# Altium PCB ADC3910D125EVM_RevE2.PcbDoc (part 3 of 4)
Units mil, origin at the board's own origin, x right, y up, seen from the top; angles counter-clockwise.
Board outline 4000 x 2716.54 mil, 6 copper layers (Top Layer, L2 GND, L3 PWR, L4 PWR, L5 GND, Bottom Layer), stack 60.99 mil thick; 318 components, 203 nets, 1298 pads, 559 vias.
Unrouted connection lines stored in the file: 5.
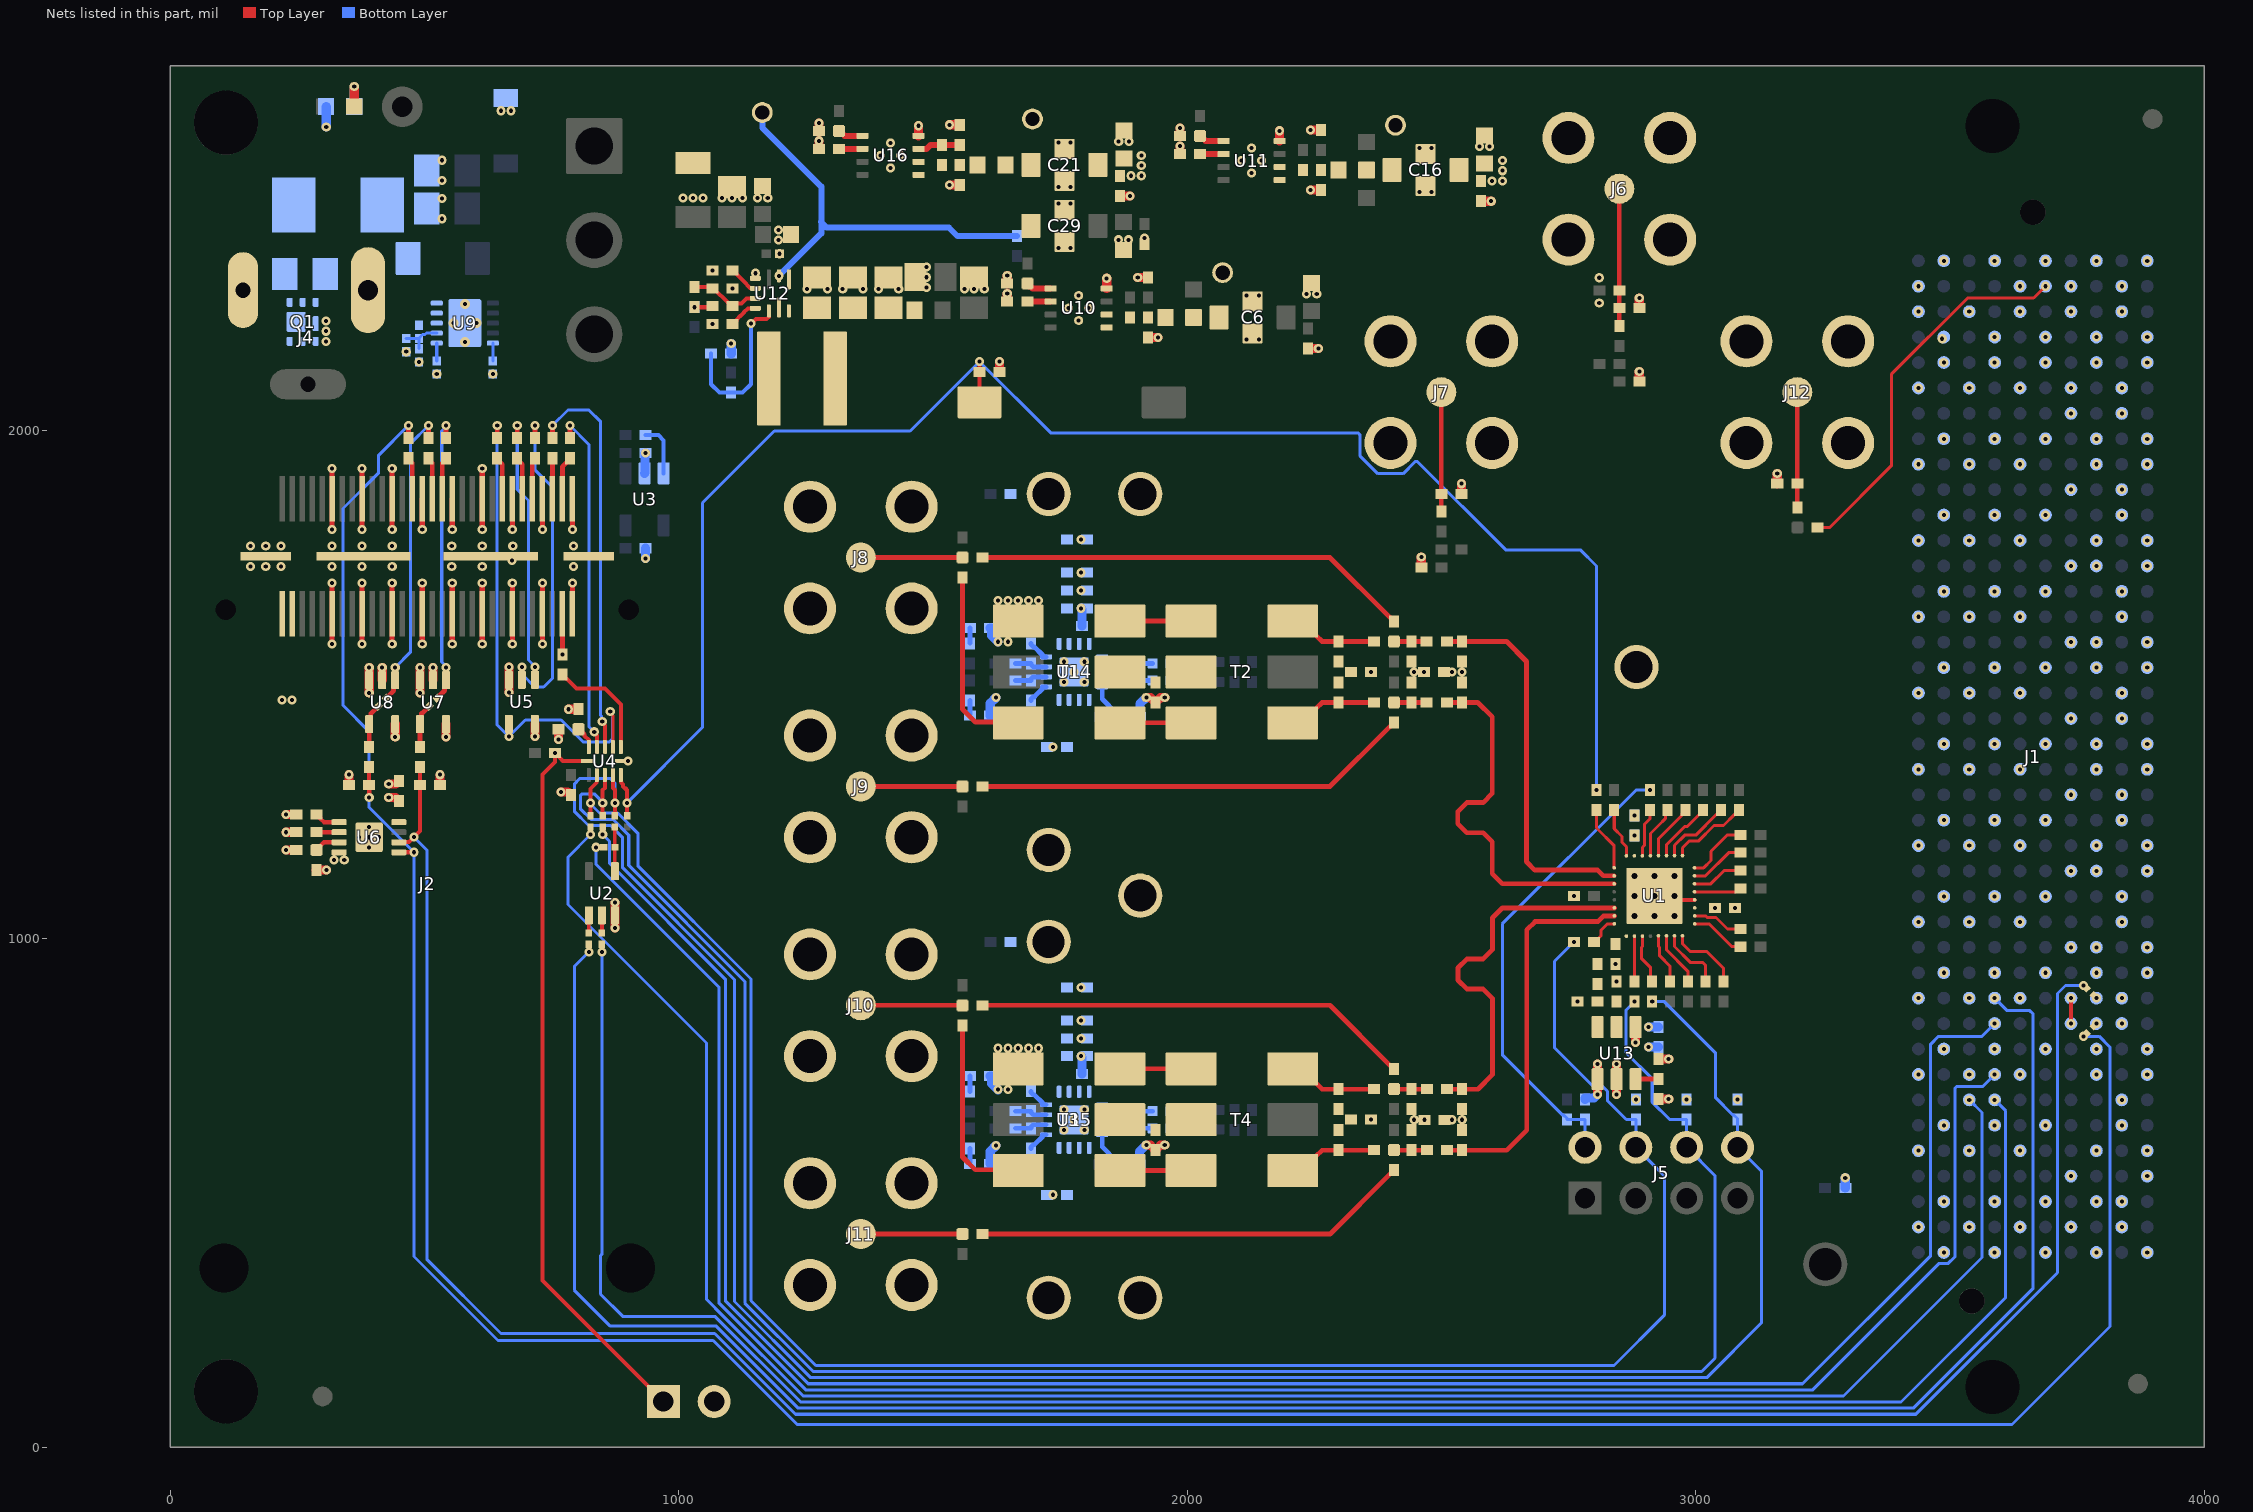
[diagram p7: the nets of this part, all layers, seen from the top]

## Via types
v1: diameter 18, hole 8, Top Layer to Bottom Layer, tented both sides, 546 vias
v2: diameter 23.62, hole 11.81, Top Layer to Bottom Layer, tented both sides, 9 vias
v3: diameter 19.68, hole 7.87, Top Layer to Bottom Layer, tented both sides, 4 vias

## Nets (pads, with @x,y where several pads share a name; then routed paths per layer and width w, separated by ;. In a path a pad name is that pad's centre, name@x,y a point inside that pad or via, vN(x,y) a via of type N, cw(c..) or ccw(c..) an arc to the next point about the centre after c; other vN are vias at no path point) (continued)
FMC_S\E\N\/M0: J1.H34 R6.1 | length 4080.2
  Top Layer w6: v1(826.87,1204.92) R6.1@826.87,1219.92
  Bottom Layer w6: v1(826.87,1204.92) 782.48,1160.53 782.48,1067.52 1055,795 1055,291.06 1089.01,257.05 1245.06,101 3291,101 3563.19,373.19 3563.19,658.27 v1(3538.19,683.27)
FMC_SCL: R22.1 R23.2 R134.1 U6.6 | length 5072.7
  Top Layer w8: U6.6@449.83,1189.86 450.27,1190.3 469.99,1190.3 479.55,1199.86 v1(479.68,1199.86) 491.63,1211.81 R22.1@491.63,1302.72 R23.2@491.63,1337.72
  Bottom Layer w6: v1(479.68,1199.86) 505,1174.54 505,369.8 650.8,224 1071.15,224 1230.15,65 3433.19,65 3711.57,343.38 3711.57,892.41 3727.43,908.27 v1(3763.19,908.27)
FMC_SCLK/M1: J1.G31 R7.1 | length 4132.5
  Top Layer w6: v1(850.87,1204.92) R7.1@850.87,1219.92
  Bottom Layer w6: v1(850.87,1204.92) 864.18,1191.61 864.18,1148.45 1092,920.64 1092,288 1255,125 3210.46,125 3462.2,376.74 3462.2,792.69 3477.79,808.27 3563.19,808.27 v1(3588.19,833.27)
FMC_SDI: J1.G34 R2.1 | length 4023
  Top Layer w6: v1(849.28,974.21) R2.1@849.28,989.21
  Bottom Layer w6: v1(849.28,974.21) 849.28,379.46 846.56,376.74 846.56,301.1 890,257.66 1071.43,257.66 1240.09,89 3404,89 3609.79,294.79 3609.79,661.67 v1(3588.19,683.27)
FMC_SDIO/M2_EN: J1.G30 R1.1 | length 4382.6
  Top Layer w6: v1(823.69,974.21) R1.1@823.69,989.21
  Bottom Layer w6: v1(823.69,974.21) 795,945.52 795,308.99 865,238.99 1073.13,238.99 1235.12,77 3428.22,77 3663.8,312.59 3663.8,852.11 3657.31,858.6 3612.86,858.6 v1(3588.19,883.27)
FMC_SDO: J1.G33 R4.1 | length 4041.8
  Top Layer w6: v1(837.83,1179.92) R4.1@852.83,1179.92
  Bottom Layer w6: v1(837.83,1179.92) 837.83,1146.37 1080,904.19 1080,283.03 1250.03,113 3230.57,113 3479.24,361.67 3497.13,361.67 3509.79,374.32 3509.79,705.66 3513.3,709.18 3564.1,709.18 v1(3588.19,733.27)
FTDI_3V3: C5.2 J2.58 J2.60 R13.1 R20.2 R22.2 R28.2 U5.5 U6.8 U7.5 U8.5 | length 178.5
  Top Layer w18: R20.2@287.58,1135.17 v1(307.58,1135.17) ; R28.2@352.26,1302.72 v1(352.26,1322.72) ; v1(430.11,1277.64) 443.42,1277.64 447.02,1274.04 448.99,1274.04 449.83,1273.2 C5.2@449.83,1271.23 ; v1(442.81,1397.09) U8.5@442.81,1422.09 ; R22.2@531,1302.72 v1(531,1322.72) ; v1(542.81,1397.09) U7.5@542.81,1422.09 ; v1(717.48,1397.76) U5.5@717.48,1422.76 ; v1(783.5,1451.46) R13.1@803.5,1451.46
  other v1: 220.35,1469.41 240.04,1469.41
GND: C1.1 C2.1 C3.1 C4.1 C5.1 C6.2 C7.1 C8.1 C9.1 C11.2 C12.2 C13.1 C14.2 C15.2 C16.2 C17.1 C18.1 C19.1 C20.1 C21.2 C22.2 C23.2 C24.2 C25.2 C26.2 C27.1 C28.1 C29.2 C30.2 C31.2 C32.1 C33.1 C34.2 C35.2 C36.2 C38.1 C39.2 C40.1 C42.1 C43.1 C44.1 C45.1 C46.1 C47.1 C48.1 C49.1 C50.1 C55.1 C57.1 C58.1 C60.2 C63.2 C64.1 C68.1 C69.1 C70.1 C71.1 C72.1 C73.1 C77.1 C78.1 C79.1 C80.2 C82.2 C86.1 C89.1 C90.1 C91.1 C92.1 C93.1 C94.1 D1.2 J1.A1 J1.A4 J1.A5 J1.A8 J1.A9 J1.A12 J1.A13 J1.A16 J1.A17 J1.A20 J1.A21 J1.A24 J1.A25 J1.A28 J1.A29 J1.A32 J1.A33 J1.A36 J1.A37 J1.A40 J1.B2 J1.B3 J1.B6 J1.B7 J1.B10 J1.B11 J1.B14 J1.B15 J1.B18 J1.B19 J1.B22 J1.B23 J1.B26 J1.B27 J1.B30 J1.B31 J1.B34 J1.B35 J1.B38 J1.B39 J1.C1 J1.C4 J1.C5 J1.C8 J1.C9 J1.C12 J1.C13 J1.C16 J1.C17 J1.C20 J1.C21 J1.C24 J1.C25 J1.C28 J1.C29 J1.C32 J1.C33 J1.C36 J1.C38 J1.C40 J1.D2 J1.D3 J1.D6 J1.D7 J1.D10 J1.D13 J1.D16 J1.D19 J1.D22 J1.D25 J1.D28 J1.D37 J1.D39 J1.E1 J1.E4 J1.E5 J1.E8 J1.E11 J1.E14 J1.E17 J1.E20 J1.E23 J1.E26 J1.E29 J1.E32 J1.E35 J1.E38 J1.E40 J1.F2 J1.F3 J1.F6 J1.F9 J1.F12 J1.F15 J1.F18 J1.F21 J1.F24 J1.F27 J1.F30 J1.F33 J1.F36 J1.F39 J1.G1 J1.G4 J1.G5 J1.G8 J1.G11 J1.G14 J1.G17 J1.G20 J1.G23 J1.G26 J1.G29 J1.G32 J1.G35 J1.G38 J1.G40 J1.H3 J1.H6 J1.H9 J1.H12 J1.H15 J1.H18 J1.H21 J1.H24 J1.H27 J1.H30 J1.H33 J1.H36 J1.H39 J1.J1 J1.J4 J1.J5 J1.J8 J1.J11 J1.J14 J1.J17 J1.J20 J1.J23 J1.J26 J1.J29 J1.J32 J1.J35 J1.J38 J1.J40 J1.K2 J1.K3 J1.K6 J1.K9 J1.K12 J1.K15 J1.K18 J1.K21 J1.K24 J1.K27 J1.K30 J1.K33 J1.K36 J1.K39 J2.1 J2.2 J2.7 J2.8 J2.13 J2.14 J2.19 J2.20 J2.25 J2.26 J2.31 J2.32 J2.37 J2.38 J2.43 J2.44 J2.49 J2.50 J2.MP1 J2.MP2 J2.MP3 J2.MP4 J3.2 J6.2 J6.3 J6.4 J6.5 J7.2 J7.3 J7.4 J7.5 J8.2 J8.3 J8.4 J8.5 J9.2 J9.3 J9.4 J9.5 J10.2 J10.3 J10.4 J10.5 J11.2 J11.3 J11.4 J11.5 J12.2 J12.3 J12.4 J12.5 Q1.4 Q1.7 R24.1 R25.1 R26.1 R35.1 R36.1 R37.1 R38.2 R44.1 R45.1 R46.1 R50.1 R51.1 R53.1 R74.1 R79.1 R84.1 R85.1 R86.1 R87.1 R105.1 R106.1 R128.1 R129.1 R136.1 R137.1 R138.1 R139.1 R141.1 R146.1 R147.1 T1.1 T3.1 TP4.1 TP5.1 TP6.1 U1.28 U1.33 U2.3 U3.2 U4.6 U5.3 U6.4 U6.9 U7.2 U7.3 U8.2 U8.3 U9.11 U10.4 U10.9 U11.4 U11.9 U12.4 U12.7 U13.1 U13.2 U14.17@1777.96,1524.88 U15.17@1777.96,644.11 U16.4 U16.9 | length 3394.7
  Top Layer w6: U12.7@1151.05,2298.88 v1(1151.05,2308.88)
  Top Layer w7.75: v2(2958.51,1084.49) 2966.39,1076.62 U1.28@2998.3,1076.62
  Top Layer w10: v1(318.78,1579.41) v1(318.78,1699.41) ; v1(318.78,1805) v1(318.78,1925) ; v1(377.83,1579.41) v1(377.83,1699.41) ; v1(377.83,1805) v1(377.83,1925) ; v1(436.89,1579.41) v1(436.89,1699.41) ; v1(436.89,1805) v1(436.89,1925) ; v1(495.94,1579.41) v1(495.94,1699.41) ; v1(495.94,1805) J2.31@495.94,1865 ; v1(555,1579.41) v1(555,1699.41) ; v1(555,1805) J2.25@555,1865 ; v1(614.06,1579.41) v1(614.06,1699.41) ; v1(614.06,1805) v1(614.06,1925) ; v1(673.11,1579.41) v1(673.11,1699.41) ; v1(673.11,1805) J2.13@673.11,1865 ; v1(732.17,1579.41) v1(732.17,1699.41) ; v1(732.17,1805) J2.7@732.17,1865 ; J2.2@791.22,1639.41 v1(791.22,1699.41) ; v1(791.22,1805) J2.1@791.22,1865
  Top Layer w18: v1(228.21,1174.54) R26.1@248.21,1174.54 ; v1(228.21,1209.54) R25.1@248.21,1209.54 ; v1(228.21,1244.54) R24.1@248.21,1244.54 ; v1(391.63,1483.7) U8.3@391.63,1508.7 v1(391.63,1533.7) ; U8.2@417.22,1508.7 v1(417.22,1533.7) ; v1(430.11,1304.18) 443.42,1304.18 447.02,1307.79 448.99,1307.79 449.83,1308.63 C5.1@449.83,1310.6 ; v1(491.63,1483.7) U7.3@491.63,1508.7 v1(491.63,1533.7) ; U7.2@517.22,1508.7 v1(517.22,1533.7) ; v1(666.3,1484.37) U5.3@666.3,1509.37 v1(666.3,1534.37) ; v1(764.13,1392.09) C3.1@764.13,1412.09 ; v1(768.79,1289.01) 782.09,1289.01 785.69,1285.41 787.66,1285.41 788.5,1284.57 C4.1@788.5,1282.6 ; v1(874.87,1021.26) U2.3@874.87,1046.26 v1(874.87,1071.26) ; C40.1@1276.39,2553.31 v1(1276.39,2569.31) ; R146.1@1276.39,2588.31 v1(1276.39,2604.31) ; U16.4@1471.99,2578.9 v1(1471.99,2598.9) ; v1(1532.99,2482.64) C27.1@1552.99,2482.64 ; v1(1532.99,2600.75) R147.1@1552.99,2600.75 ; R79.1@1631.32,2115 v1(1631.32,2135) ; C13.1@1646.39,2253.31 v1(1646.39,2269.31) ; R35.1@1646.39,2288.31 v1(1646.39,2304.31) ; U10.4@1841.99,2278.9 v1(1841.99,2298.9) ; C38.1@1868.11,2460.51 v1(1888.11,2460.51) ; v1(1902.99,2300.75) R36.1@1922.99,2300.75 ; v1(1919.84,594.22) 1927.97,594.22 1935.15,587.04 1937.12,587.04 C86.1@1937.96,586.2 ; v1(1919.84,1474.63) 1927.97,1474.63 1935.15,1467.45 1937.12,1467.45 C64.1@1937.96,1466.61 ; C7.1@1922.99,2182.64 v1(1942.99,2182.64) ; C86.1@1937.96,584.23 C86.1@1937.96,586.2 ; C64.1@1937.96,1464.64 C64.1@1937.96,1466.61 ; v1(1956.08,594.22) 1947.96,594.22 1940.77,587.04 1938.81,587.04 C86.1@1937.96,586.2 ; v1(1956.08,1474.63) 1947.96,1474.63 1940.77,1467.45 1938.81,1467.45 C64.1@1937.96,1466.61 ; C20.1@1986.39,2543.31 v1(1986.39,2559.31) ; R44.1@1986.39,2578.31 v1(1986.39,2594.31) ; U11.4@2181.99,2568.9 v1(2181.99,2588.9) ; C9.1@2238.11,2160.51 v1(2258.11,2160.51) ; v1(2242.99,2472.64) C17.1@2262.99,2472.64 ; v1(2242.99,2590.75) R45.1@2262.99,2590.75 ; R87.1@2460.63,1730.63 v1(2460.63,1750.63) ; R85.1@2539.37,1875 v1(2539.37,1895) ; C19.1@2578.11,2450.51 v1(2598.11,2450.51) ; v1(2807.37,694.02) U13.1@2807.37,724.02 v1(2807.37,754.02) ; v1(2844.77,694.02) U13.2@2844.77,724.02 v1(2844.77,754.02) ; R86.1@2889.37,2095.63 v1(2889.37,2115.63) ; R84.1@2889.37,2240 v1(2889.37,2260) ; R74.1@2927.18,684.65 v1(2947.18,684.65) ; R141.1@3160.63,1895 v1(3160.63,1915)
  Bottom Layer w18: v1(307.15,2596.35) R46.1@307.15,2636.35 ; U3.2@933.35,1915.37 934.33,1916.36 934.33,1954.53 935.17,1955.37 v1(935.32,1955.37) ; v1(935.32,1748.01) C2.1@935.32,1768.01 ; R50.1@1103.55,2150.6 v1(1103.55,2170.6) ; C90.1@1612.84,557.58 1612.84,582.03 v1(1624.34,593.52) ; C89.1@1612.84,729.95 1614.81,729.95 1615.65,729.1 1615.65,715.4 v1@1627.96,703.09 ; C69.1@1612.84,1438.69 1612.84,1463.14 v1(1624.34,1474.63) ; C68.1@1612.84,1611.06 1614.81,1611.06 1615.66,1610.21 1615.66,1596.51 v1(1627.96,1584.2) ; v1(1791.56,769.18) 1793.71,767.02 C78.1@1793.71,734.22 ; v1(1791.55,1649.94) 1793.71,1647.78 C55.1@1793.71,1614.99 ; R128.1@1906.35,555.87 1906.35,581.36 v1@1918.86,593.87 ; R105.1@1907.33,1436.63 1907.33,1462.12 v1(1919.84,1474.63) ; R136.1@2782.56,684.37 2782.56,686.34 2783.4,687.18 2800.53,687.18 v1(2807.37,694.02) ; v1(2907.18,787.01) C49.1@2927.18,787.01
  other v1: 3488.19,383.27 3588.19,383.27 3688.19,383.27 3788.19,383.27 3888.19,383.27 3438.19,433.27 3538.19,433.27 3638.19,433.27 3738.19,433.27 3838.19,433.27 3488.19,483.27 3588.19,483.27 3688.19,483.27 3788.19,483.27 3838.19,483.27 1736.44,496.63 3738.19,533.27 3888.19,533.27 3438.19,583.27 3538.19,583.27 3638.19,583.27 3788.19,583.27 3888.19,583.27 1757.96,624.11 1797.96,624.11 3488.19,633.27 3588.19,633.27 3688.19,633.27 3838.19,633.27 1777.96,644.11 2361.71,644.29 2521.07,644.11 2541.07,644.11 1757.96,664.11 1797.96,664.11 2882.56,683.84 2982.56,683.84 3082.56,683.84 3838.19,683.27 1627.96,703.79 1647.96,703.79 3438.19,733.27 3538.19,733.27 3638.19,733.27 3788.19,733.27 3888.19,733.27 3488.19,783.27 3588.19,783.27 3688.19,783.27 3788.19,783.27 3888.19,783.27 1627.96,784.79 1647.96,784.79 1667.96,784.79 1687.96,784.79 1707.96,784.79 1791.56,804.18 3838.19,833.27 1791.56,839.18 2768,876.38 3438.19,883.27 3538.19,883.27 3638.19,883.27 3838.19,883.27 1791.56,904.18 2844.77,915.75 3488.19,933.27 3588.19,933.27 3688.19,933.27 3788.19,933.27 3888.19,933.27 2842.37,950.75 3738.19,983.27 3788.19,983.27 3888.19,983.27 3438.19,1033.27 3538.19,1033.27 3638.19,1033.27 3838.19,1033.27 3077.67,1060.87 3488.19,1083.27 3588.19,1083.27 3688.19,1083.27 3838.19,1083.27 2761.03,1084.49 3738.19,1133.27 3788.19,1133.27 3888.19,1133.27 322.58,1155.17 342.58,1155.17 3438.19,1183.27 3538.19,1183.27 3638.19,1183.27 3788.19,1183.27 3888.19,1183.27 3488.19,1233.27 3588.19,1233.27 3688.19,1233.27 3838.19,1233.27 2879.77,1242.6 3738.19,1283.27 3838.19,1283.27 3438.19,1333.27 3538.19,1333.27 3638.19,1333.27 3788.19,1333.27 3888.19,1333.27 900.28,1349.58 1736.44,1377.39 3488.19,1383.27 3588.19,1383.27 3688.19,1383.27 3788.19,1383.27 3888.19,1383.27 3738.19,1433.27 3838.19,1433.27 3438.19,1483.27 3538.19,1483.27 3638.19,1483.27 3838.19,1483.27 1757.96,1504.88 1797.96,1504.88 1777.96,1524.88 2520.7,1524.82 2540.7,1524.82 2361.34,1525 3488.19,1533.27 3588.19,1533.27 3688.19,1533.27 3788.19,1533.27 3888.19,1533.27 1757.96,1544.88 1797.96,1544.88 3738.19,1583.27 3788.19,1583.27 3888.19,1583.27 1647.96,1584.2 3438.19,1633.27 3538.19,1633.27 3638.19,1633.27 3838.19,1633.27 1627.96,1665.2 1647.96,1665.2 1667.96,1665.2 1687.96,1665.2 1707.96,1665.2 3488.19,1683.27 3588.19,1683.27 3688.19,1683.27 3838.19,1683.27 1791.55,1684.94 1791.55,1719.94 158.27,1732.2 188.27,1732.2 218.27,1732.2 318.78,1732.2 377.83,1732.2 436.89,1732.2 554.06,1732.2 614.06,1732.2 793.31,1732.2 3738.19,1733.27 3788.19,1733.27 3888.19,1733.27 672.35,1743.74 158.27,1772.2 188.27,1772.2 218.27,1772.2 318.78,1772.2 377.83,1772.2 436.89,1772.2 554.06,1772.2 614.06,1772.2 674.06,1772.2 793.31,1772.2 3438.19,1783.27 3538.19,1783.27 3638.19,1783.27 3788.19,1783.27 3888.19,1783.27 1791.55,1784.94 3488.19,1833.27 3588.19,1833.55 3688.19,1833.27 3838.19,1833.27 3738.19,1883.27 3838.19,1883.27 3438.19,1933.27 3538.19,1933.27 3638.19,1933.27 3788.19,1933.27 3888.19,1933.27 3488.19,1983.27 3588.19,1983.27 3688.19,1983.27 3788.19,1983.27 3888.19,1983.27 3738.19,2033.27 3838.19,2033.27 3438.19,2083.27 3538.19,2083.27 3638.19,2083.27 3738.19,2083.27 3838.19,2083.27 524.52,2110.51 634.76,2110.51 3488.19,2133.27 3588.19,2133.27 3688.19,2133.27 3788.19,2133.27 3888.19,2133.27 489.52,2134.51 464.52,2154.51 306.52,2174.9 3485,2180 3588.19,2183.27 3688.19,2183.27 3788.19,2183.27 3888.19,2183.27 306.52,2194.9 1066.68,2209.19 306.52,2214.9 3438.19,2233.27 3538.19,2233.27 3638.19,2233.27 3738.19,2233.27 3838.19,2233.27 2810.63,2250 2235,2268 2255,2268 1252.66,2278.02 1292.66,2278.02 1322.78,2278.02 1362.78,2278.02 1392.9,2278.02 1432.9,2278.02 1562.32,2278.02 1581.32,2278.02 1601.32,2278.02 1106.05,2279.19 1487.87,2281 3438.19,2283.27 3638.19,2283.27 3738.19,2283.27 3838.19,2283.27 2810.63,2300 1487.87,2301 1066.68,2314.19 1487.87,2321 3488.19,2333.27 3588.19,2333.27 3688.19,2333.27 3788.19,2333.27 3888.19,2333.27 1198.4,2347.18 1196.87,2373.91 1865.05,2374.62 1885.05,2374.62 1916.37,2378.24 1196.87,2393.91 534.56,2416 534.56,2456 1008.44,2456.71 1028.44,2456.71 1048.44,2456.71 1085.44,2456.71 1105.44,2456.71 1125.44,2456.71 1155.44,2456.71 1175.44,2456.71 534.56,2491 534.56,2531 2575,2558 2595,2558 1865.59,2567.77 1885.59,2567.77 650.52,2628.43 670.52,2628.43
  other v2: 2879.77,1045.12 2919.14,1045.12 2958.51,1045.12 2879.77,1084.49 2919.14,1084.49 2879.77,1123.86 2919.14,1123.86 2958.51,1123.86
  other v3: 579.64,2173.46 557,2210.86 602.28,2210.86 579.64,2248.26
INAM: C63.1 R103.2 U1.11 | length 751
  Top Layer w9.5: R103.2@2510.7,1464.7 C63.1@2540.7,1464.7 2571.74,1464.7 2600,1436.44 2600,1350.06 2600,1285.81 2582.15,1267.96 2550.26,1267.96 2532.41,1250.11 2532.41,1226.31 2550.26,1208.46 2582.15,1208.46 2600,1190.61 2600,1150.23 2600,1128.12 2620,1108.11 U1.11@2839.99,1108.11
INAP: C57.2 R91.2 U1.10 | length 751
  Top Layer w9.5: R91.2@2510.7,1584.7 C57.2@2540.7,1584.7 2628.19,1584.7 2667.56,1545.33 2667.56,1151.43 2683.94,1135.05 2807.56,1135.05 2818.75,1123.87 U1.10@2839.99,1123.86
INBM: C82.1 R125.2 U1.15 | length 751
  Top Layer w9.5: R125.2@2511.08,584.29 C82.1@2541.08,584.29 2628.57,584.29 2667.94,623.66 2667.94,1017.56 2684.31,1033.94 2807.94,1033.94 2819.12,1045.12 U1.15@2840.4,1045.12
INBP: C77.2 R114.2 U1.14 | length 751
  Top Layer w9.5: R114.2@2511.07,704.29 C77.2@2541.07,704.29 2572.11,704.29 2600.37,732.55 2600.37,818.93 2600.37,883.18 2582.52,901.03 2550.63,901.03 2532.78,918.88 2532.78,942.68 2550.63,960.53 2582.52,960.53 2600.37,978.38 2600.37,1018.76 2600.37,1040.87 2620.37,1060.88 U1.14@2840.4,1060.87
IOVDD: C16.3 C18.2 C19.2 C44.2 R70.2 U1.27 | length 20
  Bottom Layer w18: R70.2@3294.37,510 v1(3294.37,530)
  other v1: 3038.3,1060.87 2600,2490.51 2620,2490.51 2620,2510.51 2620,2530.51
NetC3_2: C3.2 R13.2 U4.11 | length 44.4
  Top Layer w8: C3.2@803.5,1412.09 805.47,1412.09 815.25,1402.31 815.25,1399.22 823.5,1390.96 U4.11@823.5,1377.09
NetC6_1: C6.1 PP2.1 R30.1 R31.1
NetC10_1: C10.1 D2.2 F1.1 J4.1 Q1.3 R34.2 U9.3 U9.4 U9.5
NetC10_2: C10.2 D2.1 J4.2 Q1.1 Q1.2 Q1.5 Q1.6 Q1.8
NetC13_2: C13.2 U10.6 | length 46
  Top Layer w12: C13.2@1685.76,2253.31 U10.6@1731.76,2253.31
NetC14_1: C14.1 R34.1 R38.1 U9.2 | length 84.9
  Bottom Layer w6: R38.1@464.52,2180.49 R34.1@489.52,2180.49 ; C14.1@489.52,2160.49 R34.1@489.52,2180.49 ; U9.2@524.52,2191.18 504.27,2191.18 501.52,2188.42 496.66,2188.42 489.52,2181.28 R34.1@489.52,2180.49
NetC15_1: C15.1 U9.1 | length 35
  Bottom Layer w6: C15.1@524.52,2136.49 U9.1@524.52,2171.49
NetC16_1: C16.1 PP3.1 R39.1 R40.2 R41.1
NetC20_2: C20.2 U11.6 | length 46
  Top Layer w12: C20.2@2025.76,2543.31 U11.6@2071.76,2543.31
NetC21_1: C21.1 C29.1 PP4.1 R142.1
NetC27_2: C27.2 R142.2 R145.2 U16.1 U16.2
NetC34_1: C34.1 C35.1 C36.1 FB1.1 L1.2 U12.3
NetC37_1: C37.1 R49.1 R52.2 | length 35.9
  Top Layer w8: v1(1031.68,2242.01) 1064.49,2242.01 R52.2@1066.68,2244.19
NetC37_2: C37.2 R52.1 R53.2 U12.9 | length 141.1
  Top Layer w8: C37.2@1031.68,2281.38 1064.49,2281.38 R53.2@1066.68,2279.19 1068.64,2279.19 1097.8,2250.03 1100.2,2250.03 R52.1@1106.05,2244.19 1111.32,2249.47 1123.39,2249.47 1133.43,2259.51 U12.9@1151.05,2259.51
NetC39_1: C39.1 U12.8 | length 60.2
  Top Layer w8: C39.1@1106.05,2314.19 1108.01,2314.19 1113.86,2308.35 1113.86,2307.18 1127.86,2293.18 1140.92,2280.11 1150.12,2280.11 U12.8@1151.05,2279.19
NetC40_2: C40.2 U16.6 | length 46
  Top Layer w12: C40.2@1315.76,2553.31 U16.6@1361.76,2553.31
NetC47_2: C47.2 R66.1 U13.6
NetC50_2: C50.2 U13.5
NetC51_2: C51.2 J6.1 R83.1 R84.2 | length 270
  Top Layer w9.5: C51.2@2850,2205 R84.2@2850,2240 R83.1@2850,2275 J6.1@2850,2475
NetC52_2: C52.2 J7.1 R85.2 | length 235
  Top Layer w9.5: C52.2@2500,1840 R85.2@2500,1875 J7.1@2500,2075
NetC53_1: C53.1 C59.1 J8.1 R90.1 | length 200
  Top Layer w9.5: J8.1@1358.43,1749.7 C59.1@1558.43,1749.7
NetC54_1: C54.1 R90.2 | length 862.1
  Top Layer w9.5: R90.2@1597.8,1749.7 2281.08,1749.7 2399.64,1631.13 2401.61,1631.13 2406.71,1626.04 C54.1@2406.71,1624.07
NetC54_2: C54.2 C56.2 R89.1 R91.1 R92.2 | length 64.6
  Top Layer w9.5: C54.2@2406.71,1584.7 R92.2@2441.33,1584.7 R91.1@2471.33,1584.7
NetC56_1: C56.1 R93.2 T2.3 | length 175.9
  Top Layer w9.5: T2.3@2207.96,1624.7 2225.46,1624.7 2253.21,1596.95 2265.46,1584.7 R93.2@2297.34,1584.7 C56.1@2367.34,1584.7
NetC58_2: C58.2 R93.1 R97.2
NetC59_2: C59.2 T1.3 | length 379.6
  Top Layer w9.5: C59.2@1558.43,1710.33 1558.43,1451.32 1583.35,1426.39 1666.28,1426.39 T1.3@1667.96,1424.7
NetC61_1: C61.1 L4.2 L5.1 | length 61.2
  Bottom Layer w9.5: L4.2@1967.88,1541.69 1995.01,1541.69 C61.1@1997.88,1544.56 L5.1@2027.88,1544.56
NetC61_2: C61.2 L2.2 L3.1 | length 61.2
  Bottom Layer w9.5: L2.2@1967.88,1508.06 1995.01,1508.06 C61.2@1997.88,1505.19 L3.1@2027.88,1505.19
NetC64_2: C64.2 T1.5 T2.5
NetC65_1: C65.1 R97.1 T2.1 | length 175.9
  Top Layer w9.5: T2.1@2207.96,1424.7 2225.46,1424.7 2253.21,1452.45 2265.46,1464.7 R97.1@2297.34,1464.7 C65.1@2367.34,1464.7
NetC65_2: C65.2 C67.2 R101.1 R103.1 R104.1 | length 64.6
  Top Layer w9.5: R104.1@2406.71,1464.7 R101.1@2441.33,1464.7 R103.1@2471.33,1464.7
NetC66_2: C66.2 J9.1 R107.1 | length 200
  Top Layer w9.5: J9.1@1358.43,1299.7 R107.1@1558.43,1299.7
NetC67_1: C67.1 R107.2 | length 862.1
  Top Layer w9.5: R107.2@1597.8,1299.7 2281.08,1299.7 2399.64,1418.27 2401.61,1418.27 2406.71,1423.36 C67.1@2406.71,1425.33
NetC68_2: C68.2 R108.1 | length 30
  Bottom Layer w9.5: R108.1@1573.47,1581.06 C68.2@1573.47,1611.06
NetC69_2: C69.2 R109.1 | length 30
  Bottom Layer w9.5: C69.2@1573.47,1438.69 R109.1@1573.47,1468.69
NetC70_2: C70.2 C71.2 C72.2 C73.2 R102.1 TP10.1 U14.5 U14.6 U14.7 U14.8
NetC74_1: C74.1 C81.1 J10.1 R113.1 | length 200
  Top Layer w9.5: J10.1@1358.43,869.29 C74.1@1558.43,869.29
NetC75_1: C75.1 R113.2 | length 862.1
  Top Layer w9.5: R113.2@1597.8,869.29 2281.08,869.29 2399.64,750.72 2401.61,750.72 2406.71,745.63 C75.1@2406.71,743.66
NetC75_2: C75.2 C76.2 R112.1 R114.1 R115.2 | length 65
  Top Layer w9.5: C75.2@2406.71,704.29 R115.2@2441.7,704.29 R114.1@2471.7,704.29
NetC76_1: C76.1 R116.2 T4.3 | length 175.9
  Top Layer w9.5: T4.3@2207.96,744.29 2225.46,744.29 2253.21,716.54 2265.46,704.29 R116.2@2297.34,704.29 C76.1@2367.34,704.29
NetC79_2: C79.2 R116.1 R119.2
NetC81_2: C81.2 T3.3 | length 379.6
  Top Layer w9.5: C81.2@1558.43,829.92 1558.42,570.91 1583.35,545.98 1666.28,545.98 T3.3@1667.96,544.29
NetC83_1: C83.1 L8.2 L9.1 | length 61.2
  Bottom Layer w9.5: L8.2@1967.88,660.93 1995.01,660.93 C83.1@1997.88,663.8 L9.1@2027.88,663.8
NetC83_2: C83.2 L6.2 L7.1 | length 61.2
  Bottom Layer w9.5: L6.2@1967.88,627.3 1995.01,627.3 C83.2@1997.88,624.43 L7.1@2027.88,624.43
NetC85_1: C85.1 R119.1 T4.1 | length 175.9
  Top Layer w9.5: T4.1@2207.96,544.29 2225.46,544.29 2253.21,572.04 2265.46,584.29 R119.1@2297.34,584.29 C85.1@2367.34,584.29
NetC85_2: C85.2 C87.2 R120.1 R125.1 R127.2 | length 65
  Top Layer w9.5: R127.2@2406.71,584.29 R125.1@2471.71,584.29
NetC86_2: C86.2 T3.5 T4.5
NetC87_1: C87.1 R130.2 | length 862.1
  Top Layer w9.5: R130.2@1597.8,419.29 2281.08,419.29 2399.64,537.86 2401.61,537.86 2406.71,542.95 C87.1@2406.71,544.92
NetC88_2: C88.2 J11.1 R130.1 | length 200
  Top Layer w9.5: J11.1@1358.43,419.29 R130.1@1558.43,419.29
NetC89_2: C89.2 R131.1 | length 30
  Bottom Layer w9.5: R131.1@1573.47,699.95 C89.2@1573.47,729.95
NetC90_2: C90.2 R132.1 | length 30
  Bottom Layer w9.5: C90.2@1573.47,557.58 R132.1@1573.47,587.58
NetC91_2: C91.2 C92.2 C93.2 C94.2 R126.1 TP12.1 U15.5 U15.6 U15.7 U15.8
NetD3_2: D3.2 R46.2 | length 80
  Top Layer w18: D3.2@362.27,2636.35 v1(362.27,2676.35)
  Bottom Layer w18: R46.2@362.27,2636.35 v1(362.27,2676.35)
NetJ1_C30: J1.C30 R134.2
  other v1: 3788.19,883.27
NetJ1_C31: J1.C31 R135.2
  other v1: 3788.19,833.27
NetJ1_E2: J1.E2 R143.2 | length 750.7
  Top Layer w6: R143.2@3239.37,1808.9 3263.9,1808.9 3385,1930 3385,2109.91 3535.09,2260 3664.92,2260 v1(3688.19,2283.27)
NetJ2_3: J2.3 R8.1 | length 86.2
  Top Layer w9.5: J2.3@771.54,1865 771.54,1928.03 786.54,1943.03 R8.1@786.54,1945
NetJ2_4: J2.4@771.54,1639.41 R15.1 | length 80
  Top Layer w9.5: v1(771.54,1559.41) J2.4@771.54,1639.41
NetJ2_5: J2.5 R10.1 | length 80
  Top Layer w9.5: J2.5@751.85,1865 R10.1@751.85,1945
NetJ2_9: J2.9 R11.1 | length 82.1
  Top Layer w9.5: J2.9@712.48,1865 712.48,1940 R11.1@717.48,1945
NetJ2_11: J2.11 R12.1 | length 84.1
  Top Layer w9.5: R12.1@682.8,1945 682.8,1943.03 692.8,1933.03 J2.11@692.8,1865
NetJ2_15: J2.15 R14.1 | length 84.1
  Top Layer w9.5: R14.1@643.43,1945 643.43,1943.03 653.43,1933.03 J2.15@653.43,1865
NetJ2_27: J2.27 R16.1 | length 83.1
  Top Layer w9.5: J2.27@535.32,1865 535.32,1935.53 542.82,1943.03 R16.1@542.82,1945
NetJ2_29: J2.29 R17.1 | length 83.1
  Top Layer w9.5: R17.1@508.13,1945 508.13,1943.03 515.63,1935.53 J2.29@515.63,1865
NetJ2_33: J2.33 R18.1 | length 83.1
  Top Layer w9.5: R18.1@468.76,1945 468.76,1943.03 476.26,1935.53 J2.33@476.26,1865
NetJ3_1: J3.1 R19.1 U4.12 | length 1456
  Top Layer w8: U4.12@821.54,1349.53 772.32,1349.53 764.66,1357.19 764.66,1359.16 758.82,1365 v1(756.85,1365) 756.85,1347.4 732.17,1322.72 732.17,327.83 J3.1@970,90
NetJ12_1: J12.1 R140.1 R141.2 | length 235
  Top Layer w9.5: R140.1@3200,1848.27 3200,1883.27 J12.1@3200,2083.27
NetL1_1: L1.1 U12.2
NetL2_1: L2.1 R95.2 | length 30
  Bottom Layer w9.5: R95.2@1902.45,1508.06 L2.1@1932.45,1508.06
NetL4_1: L4.1 R100.2 | length 30
  Bottom Layer w9.5: R100.2@1902.45,1541.69 L4.1@1932.45,1541.69
NetL6_1: L6.1 R118.2 | length 30
  Bottom Layer w9.5: R118.2@1902.45,627.3 L6.1@1932.45,627.3
NetL8_1: L8.1 R124.2 | length 30
  Bottom Layer w9.5: R124.2@1902.45,660.92 L8.1@1932.45,660.92
NetPP1_1: PP1.1 R47.1 U12.5 | length 800.4
  Bottom Layer w12: PP1.1@1164.74,2625 1164.97,2624.76 1164.97,2594.79 1280.78,2478.98 1280.78,2410 ; v1(1197.31,2303.8) 1280.78,2387.27 1280.78,2409.22 ; 1280,2410 1280.78,2409.22 ; R47.1@1665.76,2382.05 1548.45,2382.05 1531.75,2398.75 1291.25,2398.75 1280.78,2409.22
NetR1_2: R1.2 U2.1 | length 35
  Top Layer w7: R1.2@823.69,1011.26 U2.1@823.69,1046.26
NetR2_2: R2.2 U2.2 | length 35
  Top Layer w8: R2.2@849.28,1011.26 U2.2@849.28,1046.26
NetR3_1: R3.1 U3.3 | length 104.4
  Bottom Layer w8: R3.1@935.32,1990.37 960.37,1990.37 970.75,1980 U3.3@970.75,1915.37
NetR4_2: R4.2 R5.2 U2.4 | length 87
  Top Layer w7: U2.4@874.87,1132.87 R4.2@874.87,1179.92 R5.2@874.87,1219.92
NetR8_2: R8.2 U4.10 | length 679.1
  Top Layer w8: v1(834.25,1407.09) 834.25,1404.38 839.25,1399.38 U4.10@839.25,1377.09
  Top Layer w9.5: R8.2@786.54,1984.37 v1(786.54,2009.37)
  Bottom Layer w6: v1(786.54,2009.37) 823.69,1972.21 823.69,1417.65 v1(834.25,1407.09)
NetR10_2: R10.2 U4.9 | length 785.4
  Top Layer w8: v1(850,1427.09) 850,1424.38 855,1419.38 U4.9@855,1377.09
  Top Layer w9.5: R10.2@751.85,1984.37 v1(751.85,2009.37)
  Bottom Layer w6: v1(751.85,2009.37) 782.48,2040 823.69,2040 846.75,2016.94 846.75,1439.22 848.09,1437.88 848.09,1429 v1(850,1427.09)
NetR11_2: R11.2 U5.2 | length 652.7
  Top Layer w9.5: U5.2@691.89,1509.37 v1(691.89,1534.37) ; R11.2@717.48,1984.37 v1(717.48,2009.37)
  Bottom Layer w6: v1(691.89,1534.37) 692.02,1534.24 692.02,1520.81 717.48,1495.35 734.76,1495.35 752.36,1512.95 752.36,1887.39 717.48,1922.28 v1(717.48,2009.37)
NetR12_2: R12.2 U5.1 | length 539.4
  Top Layer w9.5: R12.2@682.8,1984.37 v1(682.8,2009.37) ; U5.1@717.48,1509.37 v1(717.48,1534.37)
  Bottom Layer w6: v1(682.8,2009.37) 682.8,1883.97 704.83,1861.93 704.83,1548.3 717.48,1535.65 v1(717.48,1534.37)
NetR14_2: R14.2 U4.8 U5.4 | length 1035.9
  Top Layer w6: v1(666.3,1397.76) U5.4@666.3,1422.76 ; v1(865.75,1447.09) 865.75,1443.84 870.75,1438.84 U4.8@870.75,1377.09
  Top Layer w9.5: R14.2@643.43,1984.37 v1(643.43,2009.37)
  Bottom Layer w6: v1(643.43,2009.37) 643.43,1420.63 v1(666.3,1397.76) 698.69,1430.14 769.22,1430.14 812.03,1387.34 864.18,1387.34 869.75,1392.9 869.75,1439.84 865.75,1443.84 v1(865.75,1447.09)
NetR15_2: R15.2 U4.7 | length 224.3
  Top Layer w8: R15.2@771.54,1520.04 771.54,1518.07 777.38,1512.23 779.35,1512.23 799.37,1492.2 855,1492.2 886.5,1460.7 U4.7@886.5,1377.09
NetR20_1: R20.1 R26.2 U6.3 | length 52.5
  Top Layer w8: R20.1@287.58,1174.54 287.58,1176.51 293.42,1182.35 295.39,1182.35 302.89,1189.86 U6.3@332.58,1189.86
NetR21_2: R21.2 R23.1 U7.4 | length 87.9
  Top Layer w9.5: R23.1@491.63,1377.09 U7.4@491.63,1422.09 494.76,1425.21 494.76,1442.91 R21.2@509.43,1457.59
NetR24_2: R24.2 U6.1 | length 52.5
  Top Layer w8: R24.2@287.58,1244.54 289.55,1244.54 295.39,1238.7 295.39,1236.73 302.89,1229.23 U6.1@332.58,1229.23
NetR25_2: R25.2 U6.2 | length 45
  Top Layer w8: R25.2@287.58,1209.54 U6.2@332.58,1209.54
NetR27_2: R27.2 R29.1 U8.4 | length 87.9
  Top Layer w9.5: R29.1@391.63,1377.09 U8.4@391.63,1422.09 394.76,1425.21 394.76,1442.91 R27.2@409.43,1457.59
NetR32_1: R32.1 R35.2 U10.5 | length 51.1
  Top Layer w12: R32.1@1685.76,2288.31 1685.76,2286.34 1689.6,2282.49 1693.03,2282.49 1696.63,2278.9 U10.5@1731.76,2278.9
NetR37_2: R37.2 U9.10 | length 35
  Bottom Layer w6: R37.2@634.76,2136.49 U9.10@634.76,2171.49
NetR42_1: R42.1 R44.2 U11.5 | length 51.1
  Top Layer w12: R42.1@2025.76,2578.31 2025.76,2576.34 2029.6,2572.49 2033.03,2572.49 2036.63,2568.9 U11.5@2071.76,2568.9
NetR48_1: R48.1 R50.2 U12.1 | length 324.1
  Top Layer w8: v1(1142.62,2209.9) 1143.74,2209.9 1152.31,2218.46 1172.93,2218.46 1177.62,2223.15 U12.1@1177.62,2234.9
  Bottom Layer w8: R50.2@1064.18,2150.6 1064.18,2121.62 1063.82,2121.26 1063.82,2105.52 1064.18,2105.16 1064.18,2090.51 1080.67,2074.02 R48.1@1102.82,2074.02 1126.13,2074.02 1142.62,2090.51 v1(1142.62,2209.9)
NetR51_2: R51.2 U12.10 | length 59.3
  Top Layer w8: R51.2@1106.05,2209.19 1108.01,2209.19 1113.86,2215.03 1113.86,2217 1121.2,2224.35 1122,2224.35 1129.11,2231.46 1129.11,2232.26 1136.22,2239.37 1150.59,2239.37 U12.10@1151.05,2239.82
NetR54_1: R54.1 U1.4 | length 112
  Top Layer w6: U1.4@2927.02,1163.64 2927.02,1196.86 2973.22,1243.06 2973.22,1246.8 R54.1@2980.06,1253.64
NetR55_1: R55.1 U1.3 | length 123.3
  Top Layer w6: U1.3@2942.77,1163.64 2942.77,1185.02 2978.72,1220.98 2983.84,1220.98 3007.7,1244.83 3008.22,1244.83 3015.06,1251.68 R55.1@3015.06,1253.64
NetR56_1: R56.1 U1.2 | length 141.8
  Top Layer w6: U1.2@2958.51,1163.64 2958.51,1183.8 2978.64,1203.92 3000.34,1203.92 3041.25,1244.83 3043.22,1244.83 3050.06,1251.68 R56.1@3050.06,1253.64
NetR57_1: R57.1 U1.1 | length 158.2
  Top Layer w6: U1.1@2974.26,1163.64 2974.26,1178.98 2987.2,1191.92 3005.31,1191.92 3036.23,1222.84 3054.77,1222.84 3076.76,1244.83 3078.22,1244.83 3085.06,1251.68 R57.1@3085.06,1253.64
NetR58_1: R58.1 U1.32 | length 127.3
  Top Layer w6: U1.32@2997.88,1139.61 3015.84,1139.61 3030.26,1154.03 3030.26,1171.99 3062.64,1204.36 R58.1@3087.88,1204.36
NetR59_1: R59.1 U1.31 | length 108.8
  Top Layer w6: U1.31@2997.88,1123.86 3019.6,1123.86 3065.1,1169.36 R59.1@3087.88,1169.36
NetR60_1: R60.1 U1.26 | length 100.3
  Top Layer w6: U1.26@2998.3,1045.12 3019.66,1045.12 3022.76,1042.03 3040.26,1042.03 3062.92,1019.36 R60.1@3087.88,1019.36
NetR61_1: R61.1 U1.25 | length 108.2
  Top Layer w6: U1.25@2998.3,1029.37 3026.38,1029.37 3070.59,985.17 3087.08,985.17 R61.1@3087.88,984.36
NetR62_1: R62.1 U1.24 | length 142.5
  Top Layer w6: U1.24@2974.26,1005.75 2974.26,990 2989.27,975 3022.01,975 3054.77,942.24 R62.1@3054.77,915.75
NetR63_1: R63.1 U1.23 | length 129.5
  Top Layer w6: U1.23@2958.51,1005.75 2958.51,984.78 2989.56,953.73 3013.63,953.73 3019.77,947.59 R63.1@3019.77,915.75
NetR64_1: R64.1 U1.22 | length 107.4
  Top Layer w6: U1.22@2942.77,1005.75 2942.77,978.3 2984.77,936.29 R64.1@2984.77,915.75
NetR65_1: R65.1 U1.21 | length 99.4
  Top Layer w6: U1.21@2927.02,1005.75 2927.02,985.05 2929.27,982.8 2929.27,966.69 2949.77,946.18 R65.1@2949.77,915.75
NetR67_1: R67.1 U1.30 | length 100.9
  Top Layer w6: U1.30@2997.88,1108.11 3030,1108.11 3056.25,1134.36 R67.1@3087.88,1134.36
NetR68_1: R68.1 R74.2 U13.3 | length 45
  Top Layer w9.5: U13.3@2882.18,724.02 R68.1@2927.18,724.02
NetR69_2: R69.2 U1.8 | length 100.3
  Top Layer w6: R69.2@2840.06,1253.64 2840.06,1216.52 2855.23,1201.35 2855.23,1189.63 2864.03,1180.83 U1.8@2864.03,1163.23
NetR71_1: R71.1 U1.29 | length 92.9
  Top Layer w6: U1.29@2997.88,1092.37 3078.92,1092.37 3085.91,1099.36 R71.1@3087.88,1099.36
NetR72_2: R72.2 U1.5 | length 104.4
  Top Layer w6: U1.5@2911.27,1163.23 2911.27,1207.06 2926.95,1222.75 2926.95,1222.84 2940.46,1236.35 2940.46,1249.04 R72.2@2945.06,1253.64
NetR73_2: R73.2 U1.6 | length 96.4
  Top Layer w6: U1.6@2895.52,1163.23 2895.52,1179.9 2899.27,1183.65 2899.27,1224.73 2910.06,1235.52 R73.2@2910.06,1253.64
NetR75_2: R75.2 U1.18 | length 89.6
  Top Layer w6: R75.2@2879.77,915.75 U1.18@2879.77,1005.34
NetR76_2: R76.2 U1.19 | length 99.1
  Top Layer w6: U1.19@2895.52,1005.05 2895.52,985.05 2893.27,982.8 2893.27,961.65 2911.57,943.35 2911.57,918.96 R76.2@2914.77,915.75
NetR77_2: R77.2 U1.16 | length 61.1
  Top Layer w6: R77.2@2800.4,994.11 2802.37,994.11 2813.59,1005.33 2813.59,1016.35 2826.61,1029.37 U1.16@2840.4,1029.37
NetR78_2: R78.2 U1.9 | length 128.5
  Top Layer w6: R78.2@2805.06,1253.64 2805.06,1218.01 2839.99,1183.08 U1.9@2839.99,1139.61
NetR88_1: R88.1 R94.2 U14.2 | length 64
  Bottom Layer w9.5: R94.2@1662.84,1508.06 R88.1@1692.84,1508.06 1692.84,1509.94 1697.94,1515.03 U14.2@1722.84,1515.03
NetR88_2: R88.2 U14.1 | length 44.4
  Bottom Layer w9.5: R88.2@1692.84,1468.69 1692.84,1470.66 1697.94,1475.76 1699.91,1475.76 1715.78,1491.63 1715.78,1495.32 U14.1@1722.84,1495.35
NetR95_1: R95.1 U14.11 | length 32.9
  Bottom Layer w9.5: U14.11@1833.08,1515.03 1854.14,1515.03 1861.11,1508.06 R95.1@1863.08,1508.06
NetR98_2: R98.2 R105.2 U14.12 | length 74.3
  Bottom Layer w9.5: U14.12@1833.08,1495.35 1833.08,1471.52 1860.9,1443.7 1860.9,1441.73 1865.99,1436.63 R105.2@1867.96,1436.63
NetR99_2: R99.2 R110.1 U14.3 | length 64
  Bottom Layer w9.5: R99.2@1662.84,1541.69 R110.1@1692.84,1541.69 1692.84,1539.81 1697.94,1534.72 U14.3@1722.84,1534.72
NetR100_1: R100.1 U14.10 | length 32.9
  Bottom Layer w9.5: U14.10@1833.08,1534.72 1854.14,1534.72 1861.11,1541.69 R100.1@1863.08,1541.69
NetR106_2: R106.2 TP9.1 U14.13 U14.14 U14.15 U14.16
NetR110_2: R110.2 U14.4 | length 44.4
  Bottom Layer w9.5: R110.2@1692.84,1581.06 1692.84,1579.09 1697.94,1574 1699.91,1574 1715.78,1558.12 U14.4@1715.78,1554.43 ; U14.4@1715.81,1554.4 U14.4@1722.84,1554.4
NetR111_1: R111.1 U15.1 | length 44.4
  Bottom Layer w9.5: R111.1@1692.85,587.93 1692.85,589.9 1697.94,594.99 1699.91,594.99 1715.78,610.87 U15.1@1715.78,614.56 ; U15.1@1715.81,614.59 U15.1@1722.85,614.59
NetR111_2: R111.2 R117.2 U15.2 | length 64
  Bottom Layer w9.5: R117.2@1662.85,627.3 R111.2@1692.85,627.3 1692.85,629.18 1697.94,634.27 U15.2@1722.85,634.27
NetR118_1: R118.1 U15.11 | length 32.9
  Bottom Layer w9.5: U15.11@1833.08,634.27 1854.15,634.27 1861.11,627.3 R118.1@1863.08,627.3
NetR122_2: R122.2 R128.2 U15.12 | length 74.3
  Bottom Layer w9.5: U15.12@1833.08,614.59 1833.08,590.76 1860.9,562.93 1860.9,560.97 1865.99,555.87 R128.2@1867.96,555.87
NetR123_2: R123.2 R133.2 U15.3 | length 64
  Bottom Layer w9.5: R123.2@1662.85,660.92 R133.2@1692.85,660.92 1692.85,659.05 1697.94,653.96 U15.3@1722.85,653.96
NetR124_1: R124.1 U15.10 | length 32.9
  Bottom Layer w9.5: U15.10@1833.08,653.96 1854.15,653.96 1861.11,660.92 R124.1@1863.08,660.92
NetR129_2: R129.2 TP11.1 U15.13 U15.14 U15.15 U15.16
NetR133_1: R133.1 U15.4 | length 44.4
  Bottom Layer w9.5: R133.1@1692.85,700.29 1692.85,698.33 1697.94,693.23 1699.91,693.23 1715.78,677.36 U15.4@1715.78,673.67 ; U15.4@1715.81,673.64 U15.4@1722.85,673.64
NetR144_1: R144.1 R146.2 U16.5 | length 51.1
  Top Layer w12: R144.1@1315.76,2588.31 1315.76,2586.34 1319.6,2582.49 1323.03,2582.49 1326.63,2578.9 U16.5@1361.76,2578.9
NetR145_1: R145.1 R147.2 U16.3 | length 84.3
  Top Layer w12: U16.3@1471.99,2553.31 1472.09,2553.41 1487.93,2553.41 1495.9,2561.38 R145.1@1517.99,2561.38 R147.2@1552.99,2561.38
NetT1_4: T1.4 T2.6 | length 140
  Top Layer w9.5: T1.4@1867.96,1424.7 T2.6@2007.96,1424.7
NetT1_6: T1.6 T2.4 | length 140
  Top Layer w9.5: T1.6@1867.96,1624.7 T2.4@2007.96,1624.7
NetT3_4: T3.4 T4.6 | length 140
  Top Layer w9.5: T3.4@1867.96,544.29 T4.6@2007.96,544.29
NetT3_6: T3.6 T4.4 | length 140
  Top Layer w9.5: T3.6@1867.96,744.29 T4.4@2007.96,744.29
O\E\N\: J5.2 R73.1 R80.1 R136.2 | length 927.6
  Bottom Layer w6: J5.2@2782.56,590 R136.2@2782.56,645 R80.1@2747.56,645 2747.56,646.43 2740.71,653.28 2738.75,653.28 2620,772.02 2620,1029.34 2883.68,1293.01 v1(2910.06,1293.01)
OUT1: C7.2 R31.2 R33.2 U10.1 U10.2
OUT2: C17.2 R41.2 R43.2 U11.1 U11.2
REF_3p3V: C21.3 C28.2 C38.2 C49.2 R68.2 U13.4 | length 70
  Top Layer w18: v1(2882.18,796.38) U13.4@2882.18,826.38 ; R68.2@2927.18,763.39 v1(2947.18,763.39)
  Bottom Layer w18: v1(2907.18,826.38) C49.2@2927.18,826.38
  other v1: 1890,2500.51 1910,2500.51 1910,2520.51 1910,2540.51
RESET: R9.2 R78.1 R79.2 SW2.2 U4.5 | length 3340.1
  Top Layer w8: U4.5@886.5,1321.97 886.5,1307.87 891.17,1303.2 891.17,1299.74 895.86,1295.06 896.57,1295.06 898.87,1292.76 v1(898.87,1267.36) R9.2@898.87,1241.97 ; SW2.2@1591.95,2055 R79.2@1591.95,2115 v1(1591.95,2135)
  Bottom Layer w6: v1(898.87,1267.36) 1047.31,1415.79 1047.31,1857.37 1188.5,1998.56 1455.51,1998.56 v1(1591.95,2135) 1731.95,1995 2336.3,1995 2339.82,1991.49 2339.82,1950.07 2375.07,1914.82 2424.93,1914.82 2448.3,1938.19 2453.27,1938.19 2626.47,1765 2773.33,1765 2805.06,1733.27 v1(2805.06,1293.01)
S\E\N\/M0: J5.4 R6.2 R77.1 R137.2 U4.2 | length 3966.5
  Top Layer w7: R6.2@826.87,1241.97 v1(826.87,1266.97) 826.87,1294.79 838.81,1306.73 838.81,1321.53 U4.2@839.25,1321.97
  Bottom Layer w6: v1(826.87,1266.97) 826.87,1264.94 844.4,1247.42 880.21,1247.42 919.96,1207.67 919.96,1143.59 1142.46,921.09 1142.46,288.46 1269.91,161 2839.54,161 2938.54,260 2938.54,534.02 J5.4@2882.56,590 R137.2@2882.56,644.47 2863.86,644.47 2826.77,681.55 2826.77,700.07 2814.83,712.02 2796.31,712.02 2722.56,785.77 2722.56,955.64 v1(2761.03,994.11)
SCLK/M1: J5.6 R7.2 R75.1 R138.2 U4.3 | length 4066.9
  Top Layer w8: R7.2@850.87,1241.97 v1(850.87,1267.36) 850.87,1292.76 855,1296.88 U4.3@855,1321.97
  Bottom Layer w6: v1(850.87,1267.36) 850.87,1268.42 834.33,1284.97 810.51,1284.97 807,1281.45 807,1255.67 827.74,1234.92 871.03,1234.92 902.05,1203.91 902.05,1144.53 1130.46,916.12 1130.46,283.49 1264.94,149 3012,149 3038.3,175.3 3038.3,534.26 J5.6@2982.56,590 R138.2@2982.56,644.47 2948.97,644.47 2914.77,678.67 2914.77,724.54 2863.18,776.14 2863.18,859.78 v1(2879.77,876.38)
SDIO/M2: J5.8 R5.1 R76.1 R139.2 U4.4 | length 4244.1
  Top Layer w8: U4.4@870.75,1321.97 870.75,1296.88 874.87,1292.76 v1(874.87,1267.36) R5.1@874.87,1241.97
  Bottom Layer w6: v1(874.87,1267.36) 874.87,1306.43 865.75,1315.56 806.37,1315.56 795,1304.18 795,1250.7 822.77,1222.92 866.06,1222.92 890,1198.99 890,1139.61 1110.12,919.48 1110.12,286.85 1259.97,137 3022,137 3129.29,244.29 3129.29,543.27 J5.8@3082.56,590 R139.2@3082.56,644.47 3082.56,646.43 3075.71,653.28 3073.75,653.28 3038.78,688.24 3038.78,776.14 2938.54,876.38 v1(2914.77,876.38)
TDI_TDO: J1.D30 J1.D31 | length 50
  Top Layer w8: v1(3738.19,833.27) v1(3738.19,883.27)
USB_SCL: R16.2 R21.1 U7.1 | length 575.6
  Top Layer w9.5: R21.1@525.02,1473.18 539.7,1487.85 539.7,1505.59 U7.1@542.81,1508.7 v1(542.81,1533.7) ; R16.2@542.82,1984.37 v1(542.82,2009.37)
  Bottom Layer w6: v1(542.81,1533.7) 542.81,1536 534.31,1544.51 534.31,1998.56 542.82,2007.07 v1(542.82,2009.37)
USB_SDAi: R18.2 R28.1 R29.2 R135.1 U6.5 | length 6021.9
  Top Layer w8: R28.1@391.63,1302.72 R29.2@391.63,1337.72 ; U6.5@449.83,1170.17 v1(479.68,1170.17)
  Top Layer w9.5: v1(391.63,1277.72) R28.1@391.63,1302.72 ; R18.2@468.76,1984.37 v1(468.76,2009.37)
  Bottom Layer w6: v1(468.76,2009.37) 410.27,1950.88 410.27,1916.41 340,1846.14 340,1459.04 391.63,1407.4 v1(391.63,1277.72) 391.63,1258.22 v1(479.68,1170.17) 479.68,375.32 645,210 1068.18,210 1233.18,45 3622.24,45 3815,237.76 3815,787.01 3793.74,808.27 v1(3763.19,808.27)
USB_SDAo: R17.2 R27.1 U8.1 | length 595.6
  Top Layer w9.5: R27.1@425.02,1473.18 439.7,1487.85 439.7,1505.59 U8.1@442.81,1508.7 v1(442.81,1533.7) ; R17.2@508.13,1984.37 v1(508.13,2009.37)
  Bottom Layer w6: v1(442.81,1533.7) 473.31,1564.19 473.31,1974.55 v1(508.13,2009.37)
VCM: C45.2 C46.2 C55.2 C60.1 C78.2 C80.1 R92.1 R101.2 R115.1 R120.2 TP7.1 U1.7 U14.9 U15.9
  other v1: 2446.7,644.11 2466.7,644.11 2879.77,1203.23 2446.33,1524.82 2466.33,1524.82
VREF: C48.2 R66.2 U1.17
pads on no net: FID1.1 FID2.1 FID3.1 H1. H2. J1. J1.A2 J1.A3 J1.A6 J1.A7 J1.A10 J1.A11 J1.A14 J1.A15 J1.A18 J1.A19 J1.A22 J1.A23 J1.A26 J1.A27 J1.A30 J1.A31 J1.A34 J1.A35 J1.A38 J1.A39 J1.B1 J1.B4 J1.B5 J1.B8 J1.B9 J1.B12 J1.B13 J1.B16 J1.B17 J1.B20 J1.B21 J1.B24 J1.B25 J1.B28 J1.B29 J1.B32 J1.B33 J1.B36 J1.B37 J1.B40 J1.C2 J1.C3 J1.C6 J1.C7 J1.C10 J1.C11 J1.C14 J1.C15 J1.C18 J1.C19 J1.C22 J1.C23 J1.C26 J1.C27 J1.C34 J1.D1 J1.D4 J1.D5 J1.D8 J1.D9 J1.D11 J1.D12 J1.D14 J1.D15 J1.D17 J1.D18 J1.D20 J1.D21 J1.D23 J1.D24 J1.D26 J1.D27 J1.D29 J1.D33 J1.D34 J1.D35 J1.E12 J1.E13 J1.E15 J1.E16 J1.E18 J1.E19 J1.E21 J1.E22 J1.E24 J1.E25 J1.E27 J1.E28 J1.E30 J1.E31 J1.E33 J1.E34 J1.E36 J1.E37 J1.E39 J1.F1 J1.F7 J1.F8 J1.F10 J1.F11 J1.F13 J1.F14 J1.F22 J1.F23 J1.F25 J1.F26 J1.F28 J1.F29 J1.F31 J1.F32 J1.F34 J1.F35 J1.F37 J1.F38 J1.F40 J1.G2 J1.G3 J1.G6 J1.G7 J1.G9 J1.G10 J1.G12 J1.G13 J1.G15 J1.G16 J1.G18 J1.G19 J1.G21 J1.G22 J1.G24 J1.G25 J1.G36 J1.G37 J1.H1 J1.H2 J1.H4 J1.H5 J1.H7 J1.H8 J1.H10 J1.H11 J1.H13 J1.H14 J1.H16 J1.H17 J1.H19 J1.H20 J1.H22 J1.H23 J1.H25 J1.H26 J1.H28 J1.H31 J1.H32 J1.H35 J1.H37 J1.H38 J1.J2 J1.J3 J1.J6 J1.J7 J1.J9 J1.J10 J1.J12 J1.J13 J1.J15 J1.J16 J1.J18 J1.J19 J1.J24 J1.J25 J1.J27 J1.J28 J1.J30 J1.J31 J1.J33 J1.J34 J1.J36 J1.J37 J1.J39 J1.K1 J1.K4 J1.K5 J1.K7 J1.K8 J1.K10 J1.K11 J1.K13 J1.K14 J1.K17 J1.K19 J1.K20 J1.K22 J1.K23 J1.K25 J1.K26 J1.K28 J1.K29 J1.K31 J1.K32 J1.K34 J1.K35 J1.K37 J1.K38 J1.K40 J2.4@105.79,352.21 J2.4@905.79,352.2 J2.6 J2.10 J2.12 J2.16 J2.17 J2.18 J2.21 J2.22 J2.23 J2.24 J2.28 J2.30 J2.34 J2.35 J2.36 J2.39 J2.40 J2.41 J2.42 J2.45 J2.46 J2.47 J2.48 J2.51 J2.52 J2.53 J2.54 J2.55 J2.56 J2.57 J2.59 J2.MH1 J2.MH2 J4.3 LBL1.0 Q1.0 SH-J1.0 T1.2 T2.2 T3.2 T4.2 U3.4 U6.7 U9.9 U14.17@1777.96,1524.88 U15.17@1777.96,644.11

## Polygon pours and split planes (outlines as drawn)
FMC_1.8V on L3 PWR "L3 PWR-FMC_1.8V" (solid, pour order 208): 1965,2156.18 3465,2156.18 3465,369.59 3638.19,369.59 3638.19,2370.68 2200,2370.68 2200,2505 2395,2505 2395,2715 2200,2715 2200,2720 2070,2720 2070,2370.68 1965,2370.68
FMC_12V on L3 PWR "L3 PWR-FMC_12V" (solid, pour order 195): 1145,0 3465,0 4005,0 4005,683.27 3763.19,683.27 3763.19,450 3840,450 3840,265 905.79,265 905.79,891.66 188.27,891.66 188.27,1483.7 803.54,1483.7 803.54,2055 1047.31,2055 1047.31,2287.65 0,2287.65 0,0
FDA_3V3 on L3 PWR "L3_PWR_FDA_3V3_P211" (solid, pour order 211): 2070,2460 1740,2460 1740,2095 1115,2095 1115,385 1885,385 1885,2370 2070,2370 2070,2375
4V_LDO on L3 PWR "L3_PWR_4V_LDO_P210" (solid, pour order 210): 2070,2715 1115,2715 1115,2095 1740,2095 1740,2460 2070,2460
FMC_3.3V on L3 PWR "L3 PWR-FMC_3.3V" (solid, pour order 203): 2200,2370 3638.19,2370 3638.19,369.59 3840,369.59 3840,449.28 3844.82,449.28 3844.82,450 3763.19,450 3763.19,683.27 4005,683.27 4005,2715 2393.7,2715 2393.7,2505 2200,2505
GND on L3 PWR "L3_PWR_GND_P212" (solid, remove dead copper, pour order 212): 10,2710 3990,2710 3990,10 10,10
+1.8V_FTDI on L3 PWR "L3_PWR_+1.8V_FTDI_P162" (solid, pour order 162): 1047.31,1867.55 803.54,1867.55 803.54,1492.2 834.25,1492.2 834.25,1381.85 667.42,1381.85 667.42,1075.2 1047.31,1075.2
FTDI_3V3 on L3 PWR "L3 PWR-FTDI_3V3" (solid, pour order 197): 188.27,1075.2 665.66,1075.2 665.66,1381.85 834.25,1381.85 834.25,1483.7 436.89,1483.7 188.27,1483.7
+12V on L3 PWR "L3 PWR-+12V" (solid, pour order 199): 803.54,1867.55 1125.44,1867.55 1125.44,2715 0,2715 0,2283.98 1047.31,2283.98 1047.31,2055 803.54,2055
GND on L4 PWR "L4_PWR_GND_P213" (solid, remove dead copper, pour order 213): 10,2710 3990,2710 3990,10 10,10
REF_3p3V on L4 PWR "L4_PWR_REF_3P3V_P181" (solid, pour order 181): 1310,2590 1310,75 3130,75 3130,905 2860,905 2860,330 1810,330 1810,2455 1970,2455 1970,2590 1940,2590
AVDD on L4 PWR "L4 PWR-AVDD" (solid, pour order 187): 1907.96,455 2819.18,455 2819.18,1130 2590,1130 2590,614.09 2185,614.09 2185,1629.89 3195,1629.89 3195,2330.59 2320,2330.59 1907.96,2330.59
IOVDD on L4 PWR "L4 PWR-DVDD" (solid, pour order 186): 2010,2330.59 2320,2330.59 3195,2330.59 3195,1629.89 3015,1629.89 3015,1016.27 3195,1016.27 3195,515 3465,515 3465,2716.54 2070,2716.54 2010,2716.54
VCM on L4 PWR "L4_PWR_VCM_P204" (solid, pour order 204): 3015,1629.89 3015,1130 2590,1130 2590,614.09 2185,614.09 2185,1629.89
AVDD on Top Layer "TOP_LAYER_AVDD_P202" (solid, pour order 202): 2750.08,457.52 3115.04,457.52 3115.04,522.48 2750.08,522.48
GND on L2 GND "L2_GND_GND_P000" (solid, remove dead copper, pour order 0): 10,2710 3990,2710 3990,10 10,10
GND on L5 GND "L5_GND_GND_P189" (solid, remove dead copper, pour order 189): 10,2710 3990,2710 3990,10 10,10

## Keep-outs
Keep-Out Layer:
  text ".Layer_Name" at 577,-852.06 h60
